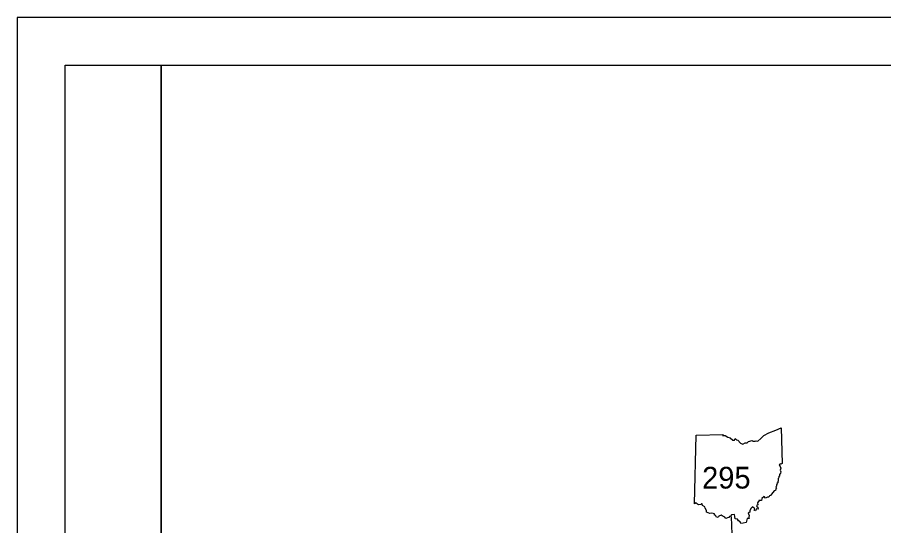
# Model space of a CAD drawing. Extents: x 0 to 750, y 0 to 507.
# Drawn here: x 0 to 180.7, y 334 to 440 of the extents above; entities that cross this region are included whole.
import ezdxf

# ---------------------------------------------------------------- set-up
doc = ezdxf.new("R2010")
doc.units = 0
for name, color, linetype in [('GM_X_Corporation_Text', 7, 'Continuous'), ('GM_X_State_Route', 7, 'Continuous'), ('SH_Border', 7, 'Continuous'), ('SH_Cut_Line', 7, 'Continuous')]:
    doc.layers.add(name, color=color, linetype=linetype)

msp = doc.modelspace()

# ---------------------------------------------------------------- linework, layer by layer
at = {"layer": 'GM_X_Corporation_Text'}
msp.add_line((141.25, 338.55), (141.65, 352.91), dxfattribs=at)
msp.add_line((141.25, 338.55), (141.65, 352.91), dxfattribs=at)
for points in [[(141.65, 352.91), (147.22, 353.01), (147.13, 352.83), (147.66, 352.8), (148.22, 352.49), (148.69, 352.3), (149.27, 351.84), (149.61, 351.85), (149.76, 352.22), (150.02, 351.93), (150.34, 351.88), (150.88, 351.19), (151.33, 351.04), (151.87, 351.28), (152.27, 351.32), (152.56, 351.55), (153.33, 351.75), (153.54, 351.63), (153.94, 351.65), (154.15, 351.74), (154.5, 351.66), (155.12, 352.19), (155.76, 352.8), (156.75, 353.38), (158.22, 353.93), (159.38, 354.43), (159.55, 346.97)], [(141.65, 352.91), (147.22, 353.01), (147.13, 352.83), (147.66, 352.8), (148.22, 352.49), (148.69, 352.3), (149.27, 351.84), (149.61, 351.85), (149.76, 352.22), (150.02, 351.93), (150.34, 351.88), (150.88, 351.19), (151.33, 351.04), (151.87, 351.28), (152.27, 351.32), (152.56, 351.55), (153.33, 351.75), (153.54, 351.63), (153.94, 351.65), (154.15, 351.74), (154.5, 351.66), (155.12, 352.19), (155.76, 352.8), (156.75, 353.38), (158.22, 353.93), (159.38, 354.43), (159.55, 346.97)], [(159.55, 346.97), (159.38, 346.87), (159.11, 346.92), (158.93, 346.71), (159.15, 346.36), (159.26, 345.99), (159.16, 345.58), (159.26, 345.25), (159.19, 344.97), (159.03, 344.69), (158.97, 344.42), (158.82, 344.14), (158.84, 343.99), (158.7, 343.86), (158.72, 343.4), (158.66, 343.14), (158.68, 342.92), (158.46, 342.86), (158.51, 342.67), (158.37, 342.53), (158.4, 342.29), (158.24, 342.13), (158.39, 341.82), (158.27, 341.72), (158.17, 341.34), (157.88, 341.26), (157.32, 340.57), (157.12, 340.3), (156.89, 340.24), (156.77, 339.97), (156.49, 339.97), (156.07, 339.78), (155.8, 340.1), (155.33, 339.71), (155.27, 339.27), (154.68, 339.28), (154.7, 339.05), (154.57, 338.99), (154.44, 338.76), (154.51, 338.36), (154.23, 338.25), (154.27, 338.02), (154.45, 337.88), (154.53, 337.43), (154.23, 337.52), (153.98, 337.14), (153.73, 337.23), (153.82, 337.55), (153.39, 337.94), (152.99, 337.63), (152.78, 337.14), (152.78, 336.81), (152.48, 336.61), (152.67, 336.14), (152.63, 335.82), (152.64, 335.51), (152.27, 335.52), (152.04, 334.7)], [(159.55, 346.97), (159.38, 346.87), (159.11, 346.92), (158.93, 346.71), (159.15, 346.36), (159.26, 345.99), (159.16, 345.58), (159.26, 345.25), (159.19, 344.97), (159.03, 344.69), (158.97, 344.42), (158.82, 344.14), (158.84, 343.99), (158.7, 343.86), (158.72, 343.4), (158.66, 343.14), (158.68, 342.92), (158.46, 342.86), (158.51, 342.67), (158.37, 342.53), (158.4, 342.29), (158.24, 342.13), (158.39, 341.82), (158.27, 341.72), (158.17, 341.34), (157.88, 341.26), (157.32, 340.57), (157.12, 340.3), (156.89, 340.24), (156.77, 339.97), (156.49, 339.97), (156.07, 339.78), (155.8, 340.1), (155.33, 339.71), (155.27, 339.27), (154.68, 339.28), (154.7, 339.05), (154.57, 338.99), (154.44, 338.76), (154.51, 338.36), (154.23, 338.25), (154.27, 338.02), (154.45, 337.88), (154.53, 337.43), (154.23, 337.52), (153.98, 337.14), (153.73, 337.23), (153.82, 337.55), (153.39, 337.94), (152.99, 337.63), (152.78, 337.14), (152.78, 336.81), (152.48, 336.61), (152.67, 336.14), (152.63, 335.82), (152.64, 335.51), (152.27, 335.52), (152.04, 334.7)], [(152.04, 334.7), (151.39, 334.54), (150.94, 334.45), (150.78, 334.82), (150.46, 335.02), (150.25, 335.4), (149.78, 335.45), (149.67, 335.96), (149.62, 336.38), (148.99, 336.28), (148.81, 336.02), (148.59, 335.95), (148.46, 335.7), (148.15, 335.67), (147.82, 335.55), (147.61, 335.81), (147.07, 336.06), (146.83, 336.19), (146.32, 335.99), (146.21, 335.75), (145.81, 335.85), (145.71, 336.12), (145.47, 336.2), (145.42, 336.49), (144.9, 336.64), (144.5, 336.58), (143.79, 336.81), (143.75, 337.19), (143.51, 337.65), (143.39, 337.97), (142.94, 338.21), (142.85, 338.59), (142.71, 338.58), (142.58, 338.42), (142.08, 338.35), (141.89, 338.51), (141.61, 338.77), (141.25, 338.55)], [(152.04, 334.7), (151.39, 334.54), (150.94, 334.45), (150.78, 334.82), (150.46, 335.02), (150.25, 335.4), (149.78, 335.45), (149.67, 335.96), (149.62, 336.38), (148.99, 336.28), (148.81, 336.02), (148.59, 335.95), (148.46, 335.7), (148.15, 335.67), (147.82, 335.55), (147.61, 335.81), (147.07, 336.06), (146.83, 336.19), (146.32, 335.99), (146.21, 335.75), (145.81, 335.85), (145.71, 336.12), (145.47, 336.2), (145.42, 336.49), (144.9, 336.64), (144.5, 336.58), (143.79, 336.81), (143.75, 337.19), (143.51, 337.65), (143.39, 337.97), (142.94, 338.21), (142.85, 338.59), (142.71, 338.58), (142.58, 338.42), (142.08, 338.35), (141.89, 338.51), (141.61, 338.77), (141.25, 338.55)]]:
    msp.add_lwpolyline(points, dxfattribs=at)
at = {"layer": 'GM_X_State_Route'}
msp.add_lwpolyline([(149.23, 327.39), (149.23, 330.47), (148.98, 335.83)], dxfattribs=at)
at = {"layer": 'SH_Border'}
for points in [[(10, 430), (30, 430), (30, 10), (10, 10)], [(30, 430), (670, 430), (670, 10), (30, 10)]]:
    msp.add_lwpolyline(points, close=True, dxfattribs=at)
at = {"layer": 'SH_Cut_Line'}
msp.add_lwpolyline([(0, 0), (680, 0), (680, 440), (0, 440)], close=True, dxfattribs=at)

# ---------------------------------------------------------------- texts
at = {"layer": 'GM_X_Corporation_Text'}
msp.add_text('295', height=4.528, dxfattribs=at).set_placement((142.86, 341.76))

doc.saveas('drawing.dxf')
